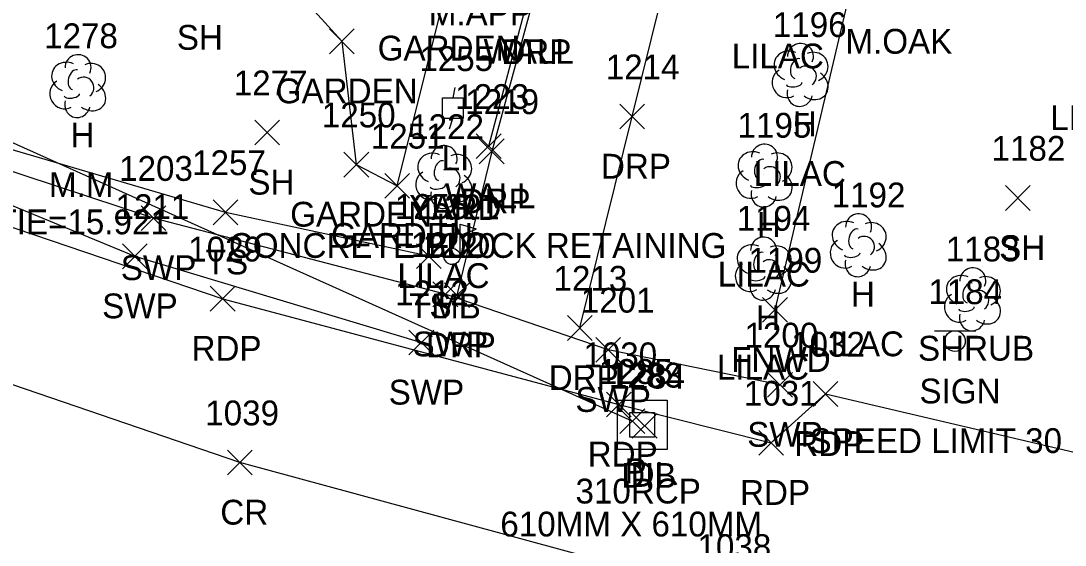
# Model space of a CAD drawing. Extents: x 1616726 to 1619875, y 273782 to 276557.
# Drawn here: x 1617199.2 to 1617283.4, y 276140.1 to 276182.4 of the extents above; entities that cross this region are included whole.
import ezdxf

# ---------------------------------------------------------------- set-up
doc = ezdxf.new("R2010")
doc.units = 0
for name, color, linetype in [('D_A', 7, 'Continuous'), ('D_C', 7, 'Continuous'), ('D_I', 7, 'Continuous'), ('D_TIC', 7, 'Continuous'), ('DCP', 7, 'Continuous'), ('DS', 7, 'Continuous'), ('L_A', 7, 'Continuous'), ('L_C', 7, 'Continuous'), ('L_I', 7, 'Continuous'), ('L_TIC', 7, 'Continuous'), ('LAPB', 7, 'Continuous'), ('LELB', 7, 'Continuous'), ('LFNC', 7, 'Continuous'), ('LMB', 7, 'Continuous'), ('LSH', 7, 'Continuous'), ('LTD', 7, 'Continuous'), ('LW', 7, 'Continuous'), ('P_A', 7, 'Continuous'), ('P_I', 7, 'Continuous'), ('P_TIC', 7, 'Continuous'), ('PET', 7, 'Continuous'), ('PRC', 7, 'Continuous'), ('R_A', 7, 'Continuous'), ('R_I', 7, 'Continuous'), ('R_TIC', 7, 'Continuous'), ('RDP', 7, 'Continuous'), ('RSW', 7, 'Continuous'), ('S_A', 7, 'Continuous'), ('S_C', 7, 'Continuous'), ('S_I', 7, 'Continuous'), ('SSGN', 7, 'Continuous'), ('U_A', 7, 'Continuous'), ('U_C', 7, 'Continuous'), ('U_I', 7, 'Continuous'), ('ULP', 7, 'Continuous')]:
    doc.layers.add(name, color=color, linetype=linetype)

msp = doc.modelspace()

# ---------------------------------------------------------------- linework, layer by layer
at = {"layer": 'D_TIC'}
for points in [[(1617247.526, 276149.098), (1617249.526, 276151.098)], [(1617249.526, 276149.098), (1617247.526, 276151.098)], [(1617248.525, 276148.723), (1617250.525, 276150.723)], [(1617250.525, 276148.723), (1617248.525, 276150.723)]]:
    msp.add_lwpolyline(points, dxfattribs=at)
at = {"layer": 'DCP'}
msp.add_lwpolyline([(1617248.526, 276150.098), (1617074.525, 276228.268)], dxfattribs=at)
at = {"layer": 'DS'}
for p, q in [((1617247.329, 276151.802), (1617251.328, 276151.802)), ((1617247.329, 276147.802), (1617247.329, 276151.802)), ((1617251.328, 276151.802), (1617251.328, 276147.802)), ((1617248.328, 276148.802), (1617248.328, 276150.802)), ((1617248.328, 276150.802), (1617250.328, 276150.802)), ((1617250.328, 276150.802), (1617250.328, 276148.802)), ((1617249.334, 276149.803), (1617249.334, 276149.803)), ((1617249.334, 276149.803), (1617249.334, 276149.803)), ((1617250.328, 276148.802), (1617248.328, 276148.802)), ((1617251.328, 276147.802), (1617247.329, 276147.802))]:
    msp.add_line(p, q, dxfattribs=at)
at = {"layer": 'L_TIC'}
for points in [[(1617224.107, 276179.716), (1617226.107, 276181.716)], [(1617226.107, 276179.716), (1617224.107, 276181.716)], [(1617218.08, 276172.36), (1617220.08, 276174.36)], [(1617220.08, 276172.36), (1617218.08, 276174.36)], [(1617235.945, 276171.259), (1617237.945, 276173.259)], [(1617237.945, 276171.259), (1617235.945, 276173.259)], [(1617225.271, 276169.776), (1617227.271, 276171.776)], [(1617227.271, 276169.776), (1617225.271, 276171.776)], [(1617228.561, 276168.066), (1617230.561, 276170.066)], [(1617230.561, 276168.066), (1617228.561, 276170.066)], [(1617278.622, 276167.085), (1617280.622, 276169.085)], [(1617280.622, 276167.085), (1617278.622, 276169.085)], [(1617214.722, 276165.925), (1617216.722, 276167.925)], [(1617216.722, 276165.925), (1617214.722, 276167.925)], [(1617231.12, 276162.4), (1617233.12, 276164.4)], [(1617233.12, 276162.4), (1617231.12, 276164.4)], [(1617259.032, 276158.065), (1617261.032, 276160.065)], [(1617261.032, 276158.065), (1617259.032, 276160.065)]]:
    msp.add_lwpolyline(points, dxfattribs=at)
at = {"layer": 'LAPB'}
msp.add_lwpolyline([(1617219.364, 276193.666), (1617218.488, 276187.997), (1617225.107, 276180.716), (1617226.271, 276170.776), (1617229.561, 276169.066), (1617233.324, 276184.167), (1617235.474, 276196.443)], dxfattribs=at)
at = {"layer": 'LELB'}
msp.add_lwpolyline([(1617232.12, 276163.4), (1617215.722, 276166.925), (1617190.258, 276174.38), (1617171.182, 276180.787), (1617154.6, 276188.638), (1617155.912, 276198.729), (1617159.607, 276211.691), (1617160.924, 276221.235)], dxfattribs=at)
at = {"layer": 'LFNC'}
msp.add_lwpolyline([(1617267.174, 276189.41), (1617260.032, 276159.065)], dxfattribs=at)
at = {"layer": 'LMB'}
for p, q in [((1617234.647, 276165.975), (1617235.941, 276165.593)), ((1617234.653, 276163.383), (1617234.652, 276165.977)), ((1617234.652, 276165.076), (1617235.935, 276165.584)), ((1617233.997, 276163.374), (1617233.997, 276163.374))]:
    msp.add_line(p, q, dxfattribs=at)
msp.add_circle((1617233.997, 276163.374), 0.656, dxfattribs=at)
at = {"layer": 'LSH'}
msp.add_line((1617275.937, 276159.975), (1617275.937, 276159.975), dxfattribs=at)
msp.add_line((1617275.937, 276159.975), (1617275.937, 276159.975), dxfattribs=at)
msp.add_arc((1617275.984, 276161.409), 1.047, 335.52715, 180.95627, dxfattribs=at)
for centre, major_axis, ratio, start_param, end_param in [((1617275.145, 276160.641), (1.21, -0.512), 0.895232, 1.570796, 4.712389), ((1617276.978, 276160.558), (-1.141, -0.483), 0.949671, 1.570796, 4.712389), ((1617275.728, 276160.433), (-0.208, -0.792), 0.645439, 3.141593, 6.283185), ((1617276.437, 276159.808), (-0.5, 0.667), 0.989748, 3.141593, 6.283185), ((1617274.854, 276159.266), (0.584, -1.042), 0.959034, 3.141593, 6.283185), ((1617276.937, 276159.142), (-1.09, 0.792), 0.841452, 1.570796, 4.712389), ((1617275.479, 276159.225), (-0.625, -0.083), 0.423636, 0, 3.141593), ((1617275.937, 276158.475), (0.265, 1.061), 0.942809, 1.570796, 4.712389)]:
    msp.add_ellipse(centre, major_axis=major_axis, ratio=ratio, start_param=start_param, end_param=end_param, dxfattribs=at)
at = {"layer": 'LTD'}
for p, q in [((1617262.041, 276178.06), (1617262.041, 276178.06)), ((1617262.041, 276178.06), (1617262.041, 276178.06)), ((1617203.79, 276177.158), (1617203.79, 276177.158)), ((1617203.79, 276177.158), (1617203.79, 276177.158)), ((1617259.14, 276169.946), (1617259.14, 276169.946)), ((1617259.14, 276169.946), (1617259.14, 276169.946)), ((1617233.31, 276169.828), (1617233.31, 276169.828)), ((1617233.31, 276169.828), (1617233.31, 276169.828)), ((1617266.728, 276164.329), (1617266.728, 276164.329)), ((1617266.728, 276164.329), (1617266.728, 276164.329)), ((1617259.07, 276162.446), (1617259.07, 276162.446)), ((1617259.07, 276162.446), (1617259.07, 276162.446))]:
    msp.add_line(p, q, dxfattribs=at)
for centre in [(1617262.088, 276179.494), (1617203.837, 276178.592), (1617259.186, 276171.38), (1617233.357, 276171.262), (1617266.775, 276165.762), (1617259.117, 276163.88)]:
    msp.add_arc(centre, 1.047, 335.52715, 180.95627, dxfattribs=at)
for centre, major_axis, ratio, start_param, end_param in [((1617261.249, 276178.726), (1.21, -0.512), 0.895232, 1.570796, 4.712389), ((1617263.082, 276178.643), (-1.141, -0.483), 0.949671, 1.570796, 4.712389), ((1617202.998, 276177.825), (1.21, -0.512), 0.895232, 1.570796, 4.712389), ((1617261.832, 276178.518), (-0.208, -0.792), 0.645439, 3.141593, 6.283185), ((1617203.581, 276177.617), (-0.208, -0.792), 0.645439, 3.141593, 6.283185), ((1617204.831, 276177.742), (-1.141, -0.483), 0.949671, 1.570796, 4.712389), ((1617260.958, 276177.351), (0.584, -1.042), 0.959034, 3.141593, 6.283185), ((1617262.541, 276177.893), (-0.5, 0.667), 0.989748, 3.141593, 6.283185), ((1617202.707, 276176.45), (0.584, -1.042), 0.959034, 3.141593, 6.283185), ((1617204.29, 276176.992), (-0.5, 0.667), 0.989748, 3.141593, 6.283185), ((1617263.041, 276177.227), (-1.09, 0.792), 0.841452, 1.570796, 4.712389), ((1617204.79, 276176.325), (-1.09, 0.792), 0.841452, 1.570796, 4.712389), ((1617262.041, 276176.56), (0.265, 1.061), 0.942809, 1.570796, 4.712389), ((1617261.583, 276177.31), (-0.625, -0.083), 0.423636, 0, 3.141593), ((1617203.79, 276175.658), (0.265, 1.061), 0.942809, 1.570796, 4.712389), ((1617203.332, 276176.408), (-0.625, -0.083), 0.423636, 0, 3.141593), ((1617232.519, 276170.494), (1.21, -0.512), 0.895232, 1.570796, 4.712389), ((1617234.352, 276170.411), (-1.141, -0.483), 0.949671, 1.570796, 4.712389), ((1617258.348, 276170.613), (1.21, -0.512), 0.895232, 1.570796, 4.712389), ((1617260.181, 276170.53), (-1.141, -0.483), 0.949671, 1.570796, 4.712389), ((1617233.102, 276170.286), (-0.208, -0.792), 0.645439, 3.141593, 6.283185), ((1617258.931, 276170.405), (-0.208, -0.792), 0.645439, 3.141593, 6.283185), ((1617232.227, 276169.119), (0.584, -1.042), 0.959034, 3.141593, 6.283185), ((1617233.81, 276169.661), (-0.5, 0.667), 0.989748, 3.141593, 6.283185), ((1617234.31, 276168.994), (-1.09, 0.792), 0.841452, 1.570796, 4.712389), ((1617258.056, 276169.238), (0.584, -1.042), 0.959034, 3.141593, 6.283185), ((1617259.64, 276169.78), (-0.5, 0.667), 0.989748, 3.141593, 6.283185), ((1617260.14, 276169.113), (-1.09, 0.792), 0.841452, 1.570796, 4.712389), ((1617232.852, 276169.078), (-0.625, -0.083), 0.423636, 0, 3.141593), ((1617258.681, 276169.196), (-0.625, -0.083), 0.423636, 0, 3.141593), ((1617233.311, 276168.328), (0.265, 1.061), 0.942809, 1.570796, 4.712389), ((1617259.14, 276168.446), (0.265, 1.061), 0.942809, 1.570796, 4.712389), ((1617265.936, 276164.995), (1.21, -0.512), 0.895232, 1.570796, 4.712389), ((1617267.769, 276164.912), (-1.141, -0.483), 0.949671, 1.570796, 4.712389), ((1617266.519, 276164.787), (-0.208, -0.792), 0.645439, 3.141593, 6.283185), ((1617267.228, 276164.162), (-0.5, 0.667), 0.989748, 3.141593, 6.283185), ((1617258.278, 276163.113), (1.21, -0.512), 0.895232, 1.570796, 4.712389), ((1617260.111, 276163.03), (-1.141, -0.483), 0.949671, 1.570796, 4.712389), ((1617265.645, 276163.62), (0.584, -1.042), 0.959034, 3.141593, 6.283185), ((1617267.728, 276163.495), (-1.09, 0.792), 0.841452, 1.570796, 4.712389), ((1617258.861, 276162.905), (-0.208, -0.792), 0.645439, 3.141593, 6.283185), ((1617259.57, 276162.28), (-0.5, 0.667), 0.989748, 3.141593, 6.283185), ((1617266.27, 276163.578), (-0.625, -0.083), 0.423636, 0, 3.141593), ((1617257.987, 276161.738), (0.584, -1.042), 0.959034, 3.141593, 6.283185), ((1617260.07, 276161.613), (-1.09, 0.792), 0.841452, 1.570796, 4.712389), ((1617266.728, 276162.829), (0.265, 1.061), 0.942809, 1.570796, 4.712389), ((1617258.612, 276161.696), (-0.625, -0.083), 0.423636, 0, 3.141593), ((1617259.07, 276160.946), (0.265, 1.061), 0.942809, 1.570796, 4.712389)]:
    msp.add_ellipse(centre, major_axis=major_axis, ratio=ratio, start_param=start_param, end_param=end_param, dxfattribs=at)
at = {"layer": 'LW'}
msp.add_lwpolyline([(1617236.945, 276172.259), (1617240.042, 276183.91), (1617245.139, 276203.477)], dxfattribs=at)
at = {"layer": 'P_TIC'}
for points in [[(1617214.497, 276158.966), (1617216.497, 276160.966)], [(1617216.497, 276158.966), (1617214.497, 276160.966)], [(1617263.103, 276151.292), (1617265.103, 276153.292)], [(1617265.103, 276151.292), (1617263.103, 276153.292)], [(1617246.442, 276150.441), (1617248.442, 276152.441)], [(1617248.442, 276150.441), (1617246.442, 276152.441)], [(1617258.727, 276147.347), (1617260.727, 276149.347)], [(1617260.727, 276147.347), (1617258.727, 276149.347)], [(1617215.872, 276145.76), (1617217.872, 276147.76)], [(1617217.872, 276145.76), (1617215.872, 276147.76)]]:
    msp.add_lwpolyline(points, dxfattribs=at)
at = {"layer": 'PET'}
msp.add_lwpolyline([(1616989.426, 276201.185), (1617018.474, 276198.311), (1617030.262, 276200.676), (1617036.67, 276206.238), (1617039.512, 276213.461), (1617039.812, 276219.435), (1617036.606, 276227.106), (1617032.436, 276230.391), (1617046.645, 276234.316), (1617061.092, 276238.884), (1617067.899, 276234.233), (1617072.399, 276230.992), (1617088.603, 276220.185), (1617112.483, 276205), (1617131.155, 276194.642), (1617156.357, 276182.31), (1617186.295, 276169.867), (1617215.497, 276159.966), (1617247.442, 276151.441), (1617259.727, 276148.347), (1617264.103, 276152.292), (1617286.332, 276147.086), (1617304.444, 276145.412), (1617352.203, 276136.042)], dxfattribs=at)
at = {"layer": 'PRC'}
msp.add_lwpolyline([(1617347.132, 276116.475), (1617295.92, 276126.996), (1617256.555, 276135.984), (1617216.872, 276146.76), (1617173.085, 276161.717), (1617139.463, 276175.956), (1617104.94, 276194.234), (1617079.375, 276210.711), (1617058.932, 276224.92), (1617047.068, 276234.028)], dxfattribs=at)
at = {"layer": 'R_TIC'}
for points in [[(1617247.51, 276173.647), (1617249.51, 276175.647)], [(1617249.51, 276173.647), (1617247.51, 276175.647)], [(1617236.191, 276170.844), (1617238.191, 276172.844)], [(1617238.191, 276170.844), (1617236.191, 276172.844)], [(1617208.918, 276165.466), (1617210.918, 276167.466)], [(1617210.918, 276165.466), (1617208.918, 276167.466)], [(1617207.417, 276162.387), (1617209.417, 276164.387)], [(1617209.417, 276162.387), (1617207.417, 276164.387)], [(1617232.448, 276159.322), (1617234.448, 276161.322)], [(1617234.448, 276159.322), (1617232.448, 276161.322)], [(1617233.39, 276159.251), (1617235.39, 276161.251)], [(1617235.39, 276159.251), (1617233.39, 276161.251)], [(1617243.299, 276156.608), (1617245.299, 276158.608)], [(1617245.299, 276156.608), (1617243.299, 276158.608)], [(1617230.52, 276155.435), (1617232.52, 276157.435)], [(1617232.52, 276155.435), (1617230.52, 276157.435)], [(1617245.579, 276154.844), (1617247.579, 276156.844)], [(1617247.579, 276154.844), (1617245.579, 276156.844)], [(1617259.434, 276152.031), (1617261.434, 276154.031)], [(1617261.434, 276152.031), (1617259.434, 276154.031)]]:
    msp.add_lwpolyline(points, dxfattribs=at)
at = {"layer": 'RDP'}
for points in [[(1617245.495, 276203.554), (1617240.479, 276183.876), (1617237.191, 276171.844), (1617234.39, 276160.251)], [(1617244.299, 276157.608), (1617248.51, 276174.647), (1617252.381, 276190.296), (1617255.015, 276201.162)]]:
    msp.add_lwpolyline(points, dxfattribs=at)
at = {"layer": 'RSW'}
for points in [[(1617260.434, 276153.031), (1617246.579, 276155.844), (1617233.448, 276160.322), (1617209.918, 276166.466), (1617188.958, 276173.374), (1617170.435, 276179.881), (1617152.678, 276188.76)], [(1617152.41, 276185.299), (1617164.585, 276179.803), (1617175.568, 276175.346), (1617187.963, 276171.838), (1617208.417, 276163.387), (1617231.52, 276156.435)]]:
    msp.add_lwpolyline(points, dxfattribs=at)
at = {"layer": 'SSGN'}
for p, q in [((1617272.899, 276157.382), (1617276.232, 276157.382)), ((1617274.545, 276156.549), (1617274.545, 276156.549))]:
    msp.add_line(p, q, dxfattribs=at)
msp.add_circle((1617274.545, 276156.549), 0.833, dxfattribs=at)
at = {"layer": 'ULP'}
for p, q in [((1617234.215, 276176.986), (1617234.048, 276176.152)), ((1617233.215, 276174.486), (1617233.215, 276176.152)), ((1617233.215, 276176.152), (1617234.881, 276176.152)), ((1617234.881, 276176.152), (1617234.881, 276174.486)), ((1617234.048, 276175.319), (1617234.048, 276175.319)), ((1617234.881, 276174.486), (1617233.215, 276174.486)), ((1617233.798, 276173.652), (1617234.048, 276174.486))]:
    msp.add_line(p, q, dxfattribs=at)

# ---------------------------------------------------------------- texts
at = {"layer": 'D_A'}
for s, p in [('DIB', (1617247.627, 276144.723)), ('P', (1617247.904, 276145.098)), ('DI', (1617248.389, 276144.803))]:
    msp.add_text(s, height=2, dxfattribs=at).set_placement(p)
at = {"layer": 'D_C'}
for s, p in [('310RCP', (1617243.949, 276143.46)), ('610MM X 610MM', (1617237.885, 276140.803))]:
    msp.add_text(s, height=2, dxfattribs=at).set_placement(p)
at = {"layer": 'D_I'}
for s, p in [('1285', (1617245.833, 276153.098)), ('1283', (1617246.641, 276152.803)), ('1284', (1617246.832, 276152.723))]:
    msp.add_text(s, height=2, dxfattribs=at).set_placement(p)
at = {"layer": 'L_A'}
for s, p in [('SH', (1617211.799, 276180.031)), ('GARDEN', (1617227.993, 276179.167)), ('WALL', (1617236.53, 276178.91)), ('GARDEN', (1617219.776, 276175.716)), ('H', (1617261.474, 276173.06)), ('H', (1617203.223, 276172.158)), ('SH', (1617217.568, 276168.36)), ('WALL', (1617233.433, 276167.259)), ('GARDEN', (1617220.94, 276165.776)), ('H', (1617232.743, 276164.828)), ('H', (1617258.573, 276164.946)), ('GARDEN', (1617224.23, 276164.066)), ('SH', (1617278.11, 276163.085)), ('TS', (1617214.131, 276161.925)), ('H', (1617266.161, 276159.329)), ('TS', (1617230.53, 276158.4)), ('MB', (1617232.304, 276158.374)), ('H', (1617258.503, 276157.446)), ('SHRUB', (1617271.567, 276154.975)), ('FNWD', (1617256.497, 276154.065))]:
    msp.add_text(s, height=2, dxfattribs=at).set_placement(p)
at = {"layer": 'L_C'}
for s, p in [('M.APP', (1617232.112, 276181.994)), ('M.OAK', (1617265.713, 276179.716)), ('LILAC', (1617256.543, 276178.532)), ('LILAC', (1617282.225, 276173.554)), ('LILAC', (1617258.316, 276169.06)), ('M.M', (1617201.491, 276168.158)), ('TIE=15.921', (1617197.254, 276165.158)), ('CONCRETE BLOCK RETAINING', (1617215.992, 276163.259)), ('LILAC', (1617229.586, 276160.828)), ('LILAC', (1617255.415, 276160.946)), ('LILAC', (1617263.003, 276155.329)), ('LILAC', (1617255.345, 276153.446))]:
    msp.add_text(s, height=2, dxfattribs=at).set_placement(p)
at = {"layer": 'L_I'}
for s, p in [('1196', (1617259.86, 276181.06)), ('1278', (1617201.097, 276180.158)), ('1277', (1617216.387, 276176.36)), ('1223', (1617234.252, 276175.259)), ('1250', (1617223.491, 276173.776)), ('1195', (1617257.014, 276172.946)), ('1222', (1617230.617, 276172.828)), ('1251', (1617227.435, 276172.066)), ('1182', (1617277.496, 276171.085)), ('1257', (1617213.029, 276169.925)), ('1192', (1617264.602, 276167.329)), ('1256', (1617229.372, 276166.4)), ('1221', (1617231.871, 276166.374)), ('1194', (1617256.944, 276165.446)), ('1183', (1617273.811, 276162.975)), ('1199', (1617257.898, 276162.065))]:
    msp.add_text(s, height=2, dxfattribs=at).set_placement(p)
at = {"layer": 'P_A'}
for s, p in [('RDP', (1617212.985, 276154.966)), ('RDP', (1617261.591, 276147.292)), ('RDP', (1617244.93, 276146.441)), ('RDP', (1617257.215, 276143.347)), ('CR', (1617215.305, 276141.76))]:
    msp.add_text(s, height=2, dxfattribs=at).set_placement(p)
at = {"layer": 'P_I'}
for s, p in [('1029', (1617212.717, 276162.966)), ('1032', (1617261.332, 276155.292)), ('1030', (1617244.583, 276154.441)), ('1031', (1617257.522, 276151.347)), ('1039', (1617214.093, 276149.76)), ('1038', (1617253.783, 276138.984))]:
    msp.add_text(s, height=2, dxfattribs=at).set_placement(p)
at = {"layer": 'R_A'}
for s, p in [('DRP', (1617237.967, 276178.876)), ('DRP', (1617245.998, 276169.647)), ('DRP', (1617234.679, 276166.844)), ('SWP', (1617207.281, 276161.466)), ('SWP', (1617205.779, 276158.387)), ('SWP', (1617230.81, 276155.322)), ('DRP', (1617231.878, 276155.251)), ('DRP', (1617241.787, 276152.608)), ('SWP', (1617228.882, 276151.435)), ('SWP', (1617243.941, 276150.844)), ('SWP', (1617257.796, 276148.031))]:
    msp.add_text(s, height=2, dxfattribs=at).set_placement(p)
at = {"layer": 'R_I'}
for s, p in [('1214', (1617246.384, 276177.647)), ('1219', (1617235.057, 276174.844)), ('1203', (1617207.147, 276169.466)), ('1211', (1617206.858, 276166.387)), ('1202', (1617230.676, 276163.322)), ('1220', (1617231.61, 276163.251)), ('1213', (1617242.173, 276160.608)), ('1212', (1617229.394, 276159.435)), ('1201', (1617244.374, 276158.844)), ('1200', (1617257.575, 276156.031))]:
    msp.add_text(s, height=2, dxfattribs=at).set_placement(p)
at = {"layer": 'S_A'}
msp.add_text('SIGN', height=2, dxfattribs=at).set_placement((1617271.683, 276151.528))
at = {"layer": 'S_C'}
msp.add_text('SPEED LIMIT 30', height=2, dxfattribs=at).set_placement((1617262.817, 276147.528))
at = {"layer": 'S_I'}
msp.add_text('1184', height=2, dxfattribs=at).set_placement((1617272.4, 276159.528))
at = {"layer": 'U_A'}
msp.add_text('LI', height=2, dxfattribs=at).set_placement((1617233.15, 276170.319))
at = {"layer": 'U_C'}
msp.add_text('YARD', height=2, dxfattribs=at).set_placement((1617230.544, 276166.319))
at = {"layer": 'U_I'}
msp.add_text('1255', height=2, dxfattribs=at).set_placement((1617231.355, 276178.319))

doc.saveas('drawing.dxf')
